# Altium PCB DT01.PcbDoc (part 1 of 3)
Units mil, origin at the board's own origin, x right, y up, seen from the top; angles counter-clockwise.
Board outline 2134.7 x 2226.1 mil, 2 copper layers (Top Layer, Bottom Layer), stack 57.918 mil thick; 95 components, 87 nets, 468 pads, 300 vias.
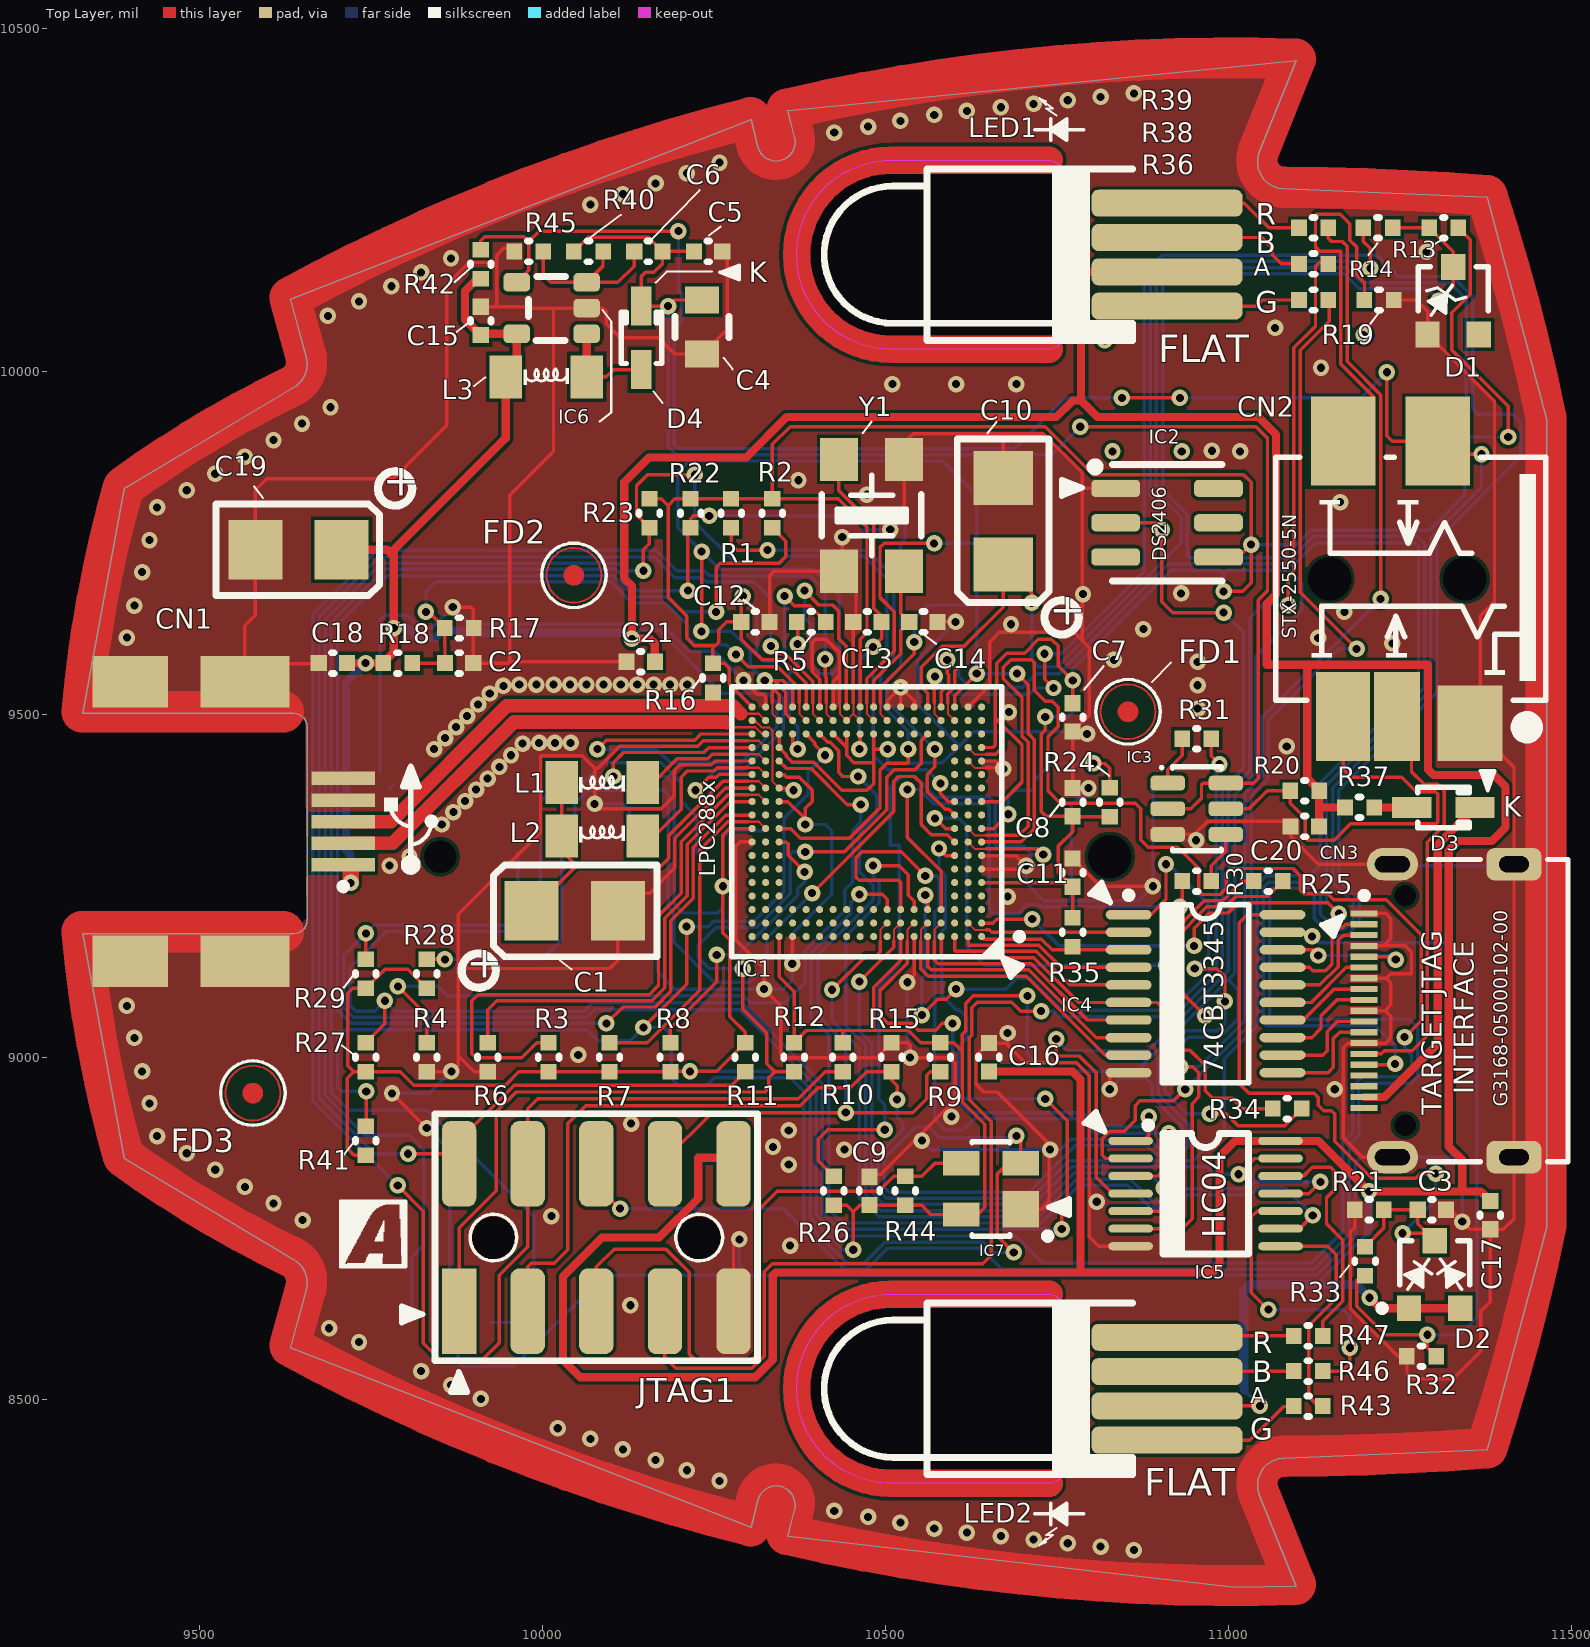
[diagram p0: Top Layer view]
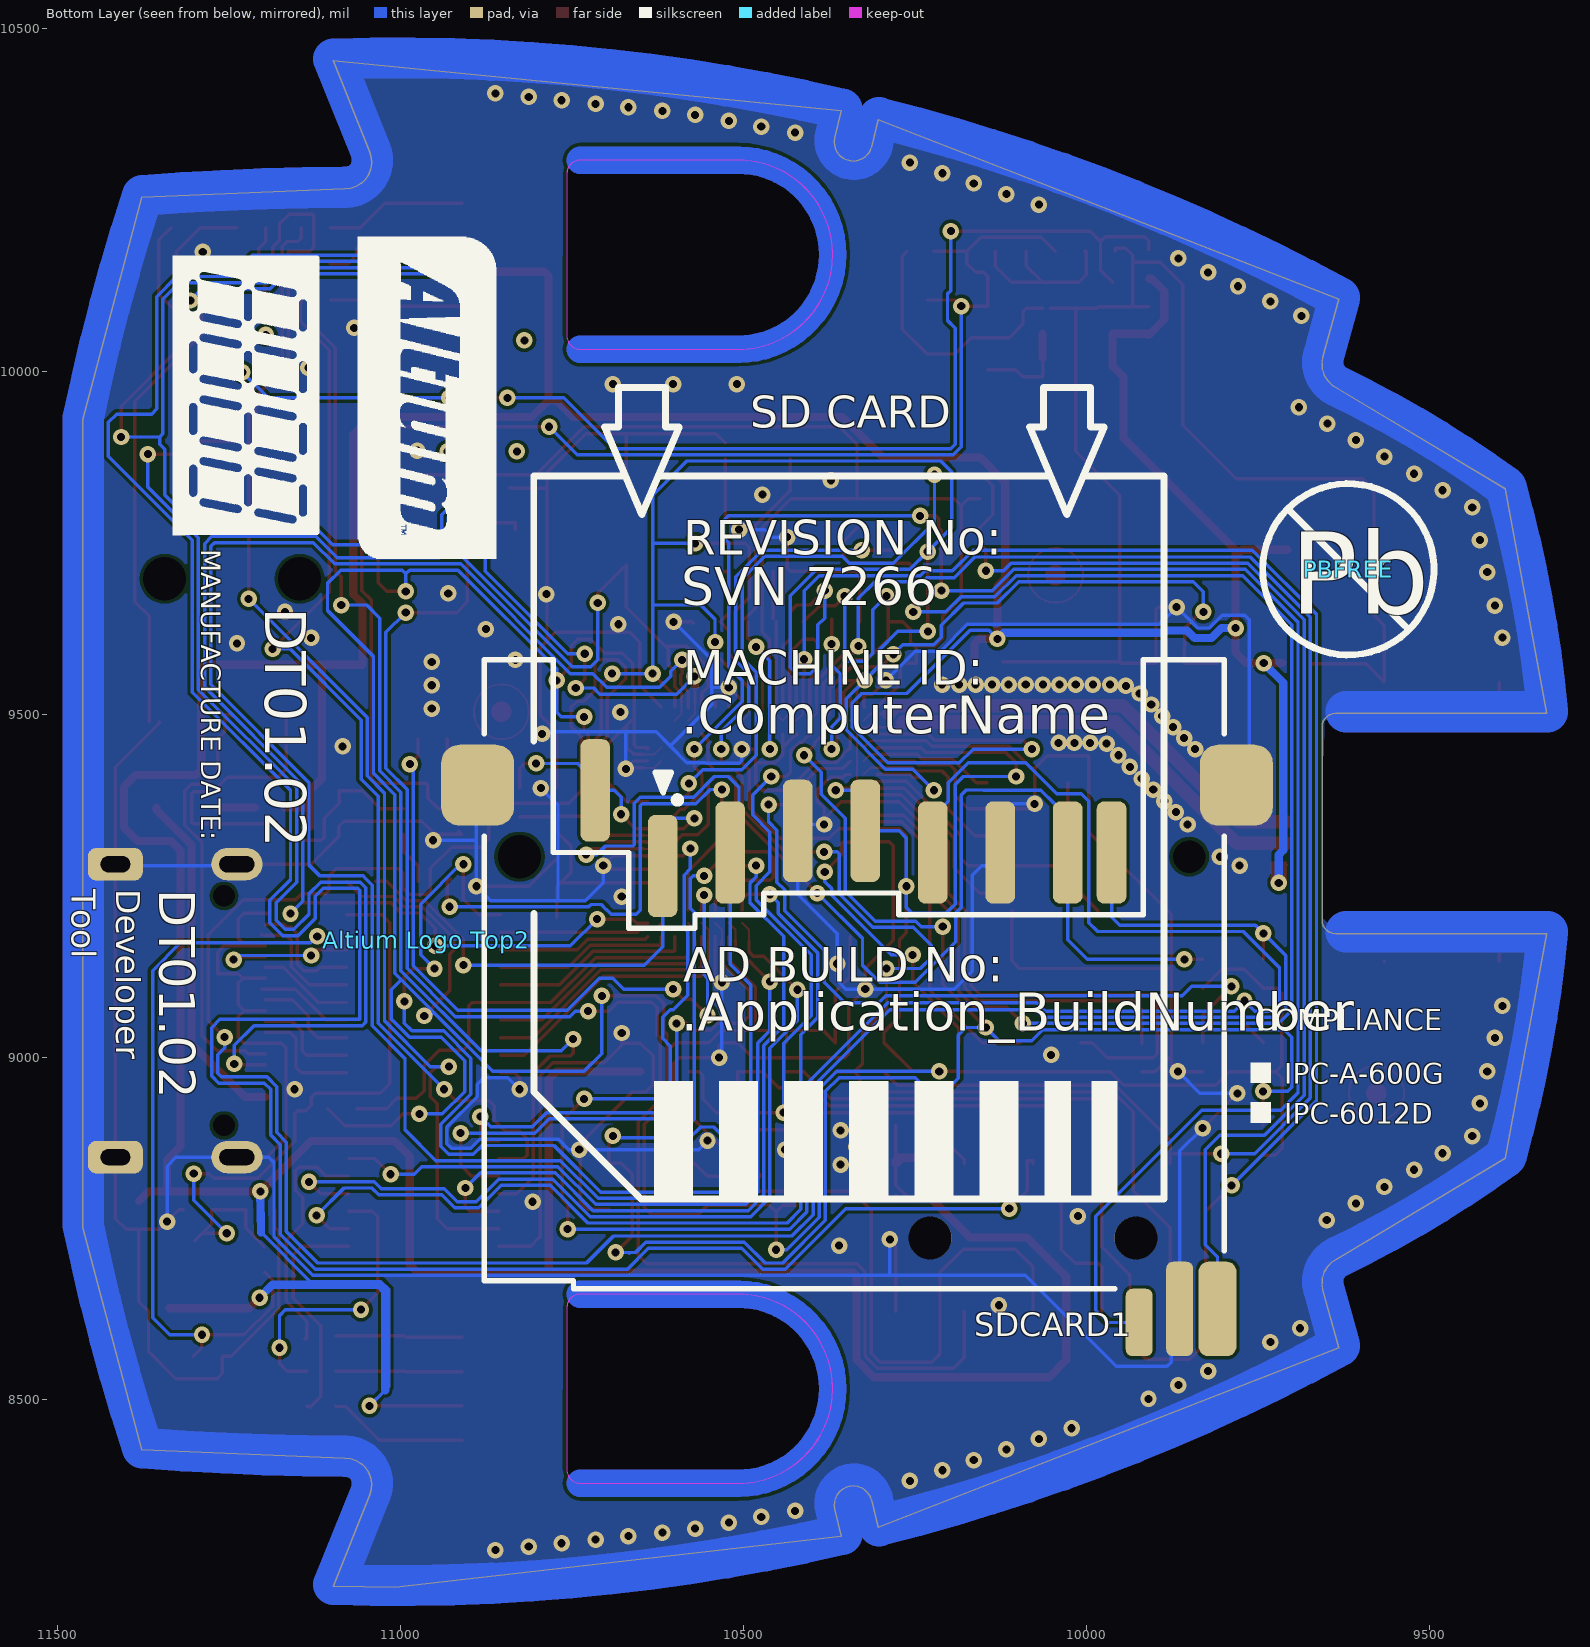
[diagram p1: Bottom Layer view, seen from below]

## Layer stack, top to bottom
Top Layer: signal copper 1.4
Dielectric: core 55.1181, FR-4, Dk 4.8
Bottom Layer: signal copper 1.4

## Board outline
9632.47,8576.36 9655.61,8660.1 9657,8669.12 9656.28,8678.21 9653.49,8686.9 9648.77,8694.71 9642.38,8701.23 9634.66,8706.09 9389.82,8852.38 9329.39,9180.02 9637.16,9180.02 9641.54,9180.52 9645.7,9181.97 9649.44,9184.32 9652.55,9187.43 9654.9,9191.17 9656.35,9195.33 9656.85,9199.71 9656.85,9481.2 9656.35,9485.58 9654.9,9489.74 9652.55,9493.48 9649.44,9496.59 9645.7,9498.94 9641.54,9500.39 9637.16,9500.89 9329.39,9500.89 9389.82,9828.53 9634.66,9974.82 9642.38,9979.68 9648.77,9986.2 9653.49,9994.01 9656.28,10002.7 9657,10011.79 9655.61,10020.81 9632.47,10104.55 10304.11,10366.84 10313.82,10327.29 10315.77,10321.87 10318.81,10316.97 10322.8,10312.81 10327.56,10309.57 10332.89,10307.39 10338.56,10306.37 10344.32,10306.55 10349.92,10307.93 10355.11,10310.43 10359.66,10313.96 10363.38,10318.36 10366.1,10323.44 10367.71,10328.97 10368.13,10334.72 10367.35,10340.43 10357.69,10379.8 11098.79,10452.79 11045.28,10319.67 11042.98,10311.48 11042.49,10302.98 11043.84,10294.58 11046.96,10286.67 11051.71,10279.61 11057.86,10273.73 11065.14,10269.32 11073.19,10266.57 11081.64,10265.62 11377.54,10253.65 11464.09,9929.39 11464.09,8751.52 11377.54,8427.26 11081.64,8415.29 11073.19,8414.34 11065.14,8411.59 11057.86,8407.18 11051.71,8401.3 11046.96,8394.24 11043.84,8386.33 11042.49,8377.93 11042.98,8369.43 11045.28,8361.24 11098.79,8228.12 11008.37,8226.7 10357.69,8301.11 10367.35,8340.48 10368.12,8345.97 10367.79,8351.49 10366.35,8356.84 10363.87,8361.79 10360.45,8366.15 10356.24,8369.74 10351.38,8372.41 10346.1,8374.06 10340.59,8374.61 10334.53,8373.94 10328.76,8371.95 10323.58,8368.74 10319.23,8364.47 10315.92,8359.35 10313.82,8353.62 10304.11,8314.07
cut-out: 10508.24,10032.02 cw(c10508.24,10169.82) 10508.24,10307.61 10738.55,10307.61 cw(c10738.55,10287.93) 10758.24,10287.93 10758.24,10051.71 cw(c10738.55,10051.71) 10738.55,10032.02
cut-out: 10508.24,8378.48 cw(c10508.24,8516.27) 10508.24,8654.07 10738.55,8654.07 cw(c10738.55,8634.38) 10758.24,8634.38 10758.24,8398.16 cw(c10738.55,8398.16) 10738.55,8378.48

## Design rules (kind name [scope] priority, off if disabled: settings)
Clearance [All] p1: gap=3
ComponentClearance [All] p1: gap=10 collisioncheckmode=3 verticalgap=9.21 showdistances=TRUE
FabricationTestPointUsage TestPointUsage [All] p1: valid=0 allowmultiple=FALSE
FabricationTestpoint Testpoint [All] p1: side=3 testpointundercomponent=TRUE minsize=40 maxsize=100 preferedsize=60 minholesize=0 maxholesize=40 preferedholesize=32 testpointgrid=1 allowsidetop=TRUE allowsidebottom=TRUE usegrid=TRUE gridtolerance=0.01
MinimumSolderMaskSliver [All] p1: minsoldermaskwidth=2.9
PolygonConnect [All] p1: connectstyle=Direct reliefconductorwidth=10 reliefentries=4 polygonreliefangle="90 Angle"
RoomDefinition U_Visual_Indicators [InComponentClass('U_Visual_Indicators')] p1: confinementstyle=ConfineIn formatcopy=TRUE lockcomponents=FALSE outline 10395.6,8376.32 10395.6,10309.87 11080.91,10309.87 11080.91,10239.02 11168.13,10239.02 11168.13,10073.73 11160.25,10073.73 11160.25,8460.95 11072.72,8460.95 11072.72,8376.32
RoomDefinition U_SD_Card_Socket [InComponentClass('U_SD_Card_Socket')] p2: confinementstyle=ConfineIn formatcopy=TRUE lockcomponents=FALSE outline 9712.34,8955.68 9712.34,9165.24 9717.12,9165.24 9717.12,9593.7 10125.87,9593.7 10125.87,9836.79 10245.89,9836.79 10245.89,9593.7 10952.72,9593.7 10952.72,9286.51 11102.19,9286.51 11102.19,9226.51 10952.72,9226.51 10952.72,8552.23 9717.12,8552.23 9717.12,8955.68
RoomDefinition U_Power_Bypass_Caps [InComponentClass('U_Power_Bypass_Caps')] p3: confinementstyle=ConfineIn formatcopy=TRUE lockcomponents=FALSE outline 9509.11,9657.72 9509.11,9821.58 10589.56,9821.58 10589.56,9916.06 10753.41,9916.06 10753.41,9539.11 10802.84,9539.11 10802.84,9366.21 11155.31,9366.21 11155.31,8813.39 11411.93,8813.39 11411.93,8725.43 11351.93,8725.43 11351.93,8760.87 10446.65,8760.87 10446.65,9544.34 9650.39,9544.34 9650.39,9657.72
RoomDefinition U_One-Wire_Write_Read [InComponentClass('U_One-Wire_Write_Read')] p4: confinementstyle=ConfineIn formatcopy=TRUE lockcomponents=FALSE outline 9879.87,10029.25 9879.87,10199.88 9935.73,10199.88 9935.73,10204.58 10285.46,10204.58 10285.46,10134.93 10286.91,10134.93 10286.91,10133.73 11263.57,10133.73 11263.57,9974.59 11553.33,9974.59 11553.33,9420.09 11155.33,9420.09 11155.33,9358.36 11032.72,9358.36 11032.72,9287.02 10997.89,9287.02 10997.89,9226.51 10909.89,9226.51 10909.89,9287.02 10875.07,9287.02 10875.07,9948.56 9911.14,9948.56 9911.14,10029.25
RoomDefinition U_Mini_USB_Socket [InComponentClass('U_Mini_USB_Socket')] p5: confinementstyle=ConfineIn formatcopy=TRUE lockcomponents=FALSE outline 9254.8,9090.36 9254.8,9595.84 9744.84,9595.84 9744.84,9604.34 9834.38,9604.34 9834.38,9655.51 9922.38,9655.51 9922.38,9596.67 10278.36,9596.67 10278.36,9508.67 9767.14,9508.67 9767.14,9090.36
RoomDefinition U_MCU_Debug [InComponentClass('U_MCU_Debug')] p6: confinementstyle=ConfineIn formatcopy=TRUE lockcomponents=FALSE outline 9816.28,8542.21 9816.28,8932.21 10336.28,8932.21 10336.28,8542.21
RoomDefinition U_MCU [InComponentClass('U_MCU')] p7: confinementstyle=ConfineIn formatcopy=TRUE lockcomponents=FALSE outline 9712.34,8834.13 9712.34,8922.13 9801.15,8922.13 9801.15,9043.68 9913.53,9043.68 9913.53,9295.14 9992.81,9295.14 9992.81,9458.72 10224.66,9458.72 10224.66,9591.16 10244.93,9591.16 10244.93,9836.79 10392.1,9836.79 10392.1,9914.33 10567.1,9914.33 10567.1,9664.36 10599.35,9664.36 10599.35,9591.16 10721.03,9591.16 10721.03,8890.64 10756.29,8890.64 10756.29,8719.06 10572.39,8719.06 10572.39,8760.85 10498.81,8760.85 10498.81,8834.13
RoomDefinition U_IO_Bus_Switch [InComponentClass('U_IO_Bus_Switch')] p8: confinementstyle=ConfineIn formatcopy=TRUE lockcomponents=FALSE outline 10742.84,9137.89 10742.84,9225.89 10799.23,9225.89 10799.23,9255.87 11134.19,9255.87 11134.19,8807.18 11340.68,8807.18 11340.68,8762.22 11367.35,8762.22 11367.35,8603.39 11325.56,8603.39 11325.56,8533.75 11237.56,8533.75 11237.56,8603.39 11204.12,8603.39 11204.12,8658.39 11169.29,8658.39 11169.29,8747.18 11161.19,8747.18 11041.74,8747.18 11041.74,8894.88 11041.74,8940.59 10799.23,8940.59 10799.23,9137.89
RoomDefinition U_Hard_Soft_JTAG_Socket [InComponentClass('U_Hard_Soft_JTAG_Socket')] p9: confinementstyle=ConfineIn formatcopy=TRUE lockcomponents=FALSE outline 11147.18,9334 11147.18,9394 11227.23,9394 11227.23,9407.23 11399.84,9407.23 11399.84,9316.28 11509.04,9316.28 11509.04,8818.87 11166.67,8818.87 11166.67,9334
RoomDefinition U_DT01_Mounts [InComponentClass('U_DT01_Mounts')] p10: confinementstyle=ConfineIn formatcopy=TRUE lockcomponents=FALSE outline 9518.12,8887.88 9518.12,9006.88 9518.12,9761.88 9986.12,9761.88 10105.12,9761.88 10105.12,9562.88 10913.12,9562.88 10913.12,9443.88 9637.12,9443.88 9637.12,8887.88
RoomDefinition DT01_ID [InComponentClass('DT01_ID')] p11: confinementstyle=ConfineIn formatcopy=TRUE lockcomponents=FALSE outline 10783.23,9679.01 10783.23,9882.81 11174.1,9882.81 11174.1,10239.02 11358.04,10239.02 11358.04,10182.16 11394.43,10182.16 11394.43,10023.33 11394.43,9679.01 11032.6,9679.01
RoutingVias [All] p1: holewidth=11.81 width=24 viastyle="Through Hole" minholewidth=11 minwidth=24 maxholewidth=12 maxwidth=28
SilkToSilkClearance SilkToSilkClearance_InvToFill [(ObjectKind = 'Text') And (TextKind <> 'Stroke Font') vs IsFill or Istrack] p1: silktosilkclearance=0
SilkToSilkClearance SilkToSilkClearance_Labels [(ObjectKind = 'Text') And (TextKind <> 'Stroke Font') vs (ObjectKind = 'Text') And (TextKind <> 'Stroke Font')] p2: silktosilkclearance=0
SilkToSilkClearance SilkToSilkClearance_Pb [(ObjectKind = 'Text') And (StringText = 'Pb') vs Istrack and onsilkscreen] p3: silktosilkclearance=0
SilkToSilkClearance SilkToSilkClearance_IC1 [incomponent('IC1') vs isdesignator] p4: silktosilkclearance=0
SilkToSilkClearance SilkToSilkClearance_+ [(ObjectKind = 'Text') And (StringText = '+') And (IsTextInverted = 'True') And (TextKind = 'TrueType Font') vs isarc and onsilkscreen] p5: silktosilkclearance=0
SilkToSilkClearance [All] p6: silktosilkclearance=4
SilkscreenOverComponentPads SilkscreenOverComponentPads_JTAG1 [isthrupin and InComponent('JTAG1') vs isarc and onsilkscreen] p1: minsilkscreentomaskgap=0
SilkscreenOverComponentPads SilkscreenOverComponentPads_LEDs [incomponent('LED1') or incomponent('LED2')] p2: minsilkscreentomaskgap=0
SilkscreenOverComponentPads [All] p3: minsilkscreentomaskgap=1
SolderMaskExpansion [All] p1: expansion=4
Width [All] p1: maxlimit=60 minlimit=3 preferedwidth=5
22 further rules are at their usual default settings.

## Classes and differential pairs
component class DT01_ID: D1 IC2 R13 R14
component class U_DT01_Mounts: FD1 FD2 FD3 PCB1
component class U_Hard_Soft_JTAG_Socket: CN3 D3 R37
component class U_IO_Bus_Switch: C3 D2 IC4 R21 R32 R33 R34 R35
component class U_MCU_Debug: JTAG1
component class U_MCU: C1 C13 C14 IC1 IC7 L1 L2 R1 R2 R3 R4 R5 R6 R7 R8 R9 R10 R11 R12 R15 R41 R44 Y1
component class U_Mini_USB_Socket: C2 CN1 R16 R17 R18
component class U_One-Wire_Write_Read: C4 C5 C6 C15 CN2 D4 IC3 IC6 L3 R19 R20 R30 R31 R40 R42 R45
component class U_Power_Bypass_Caps: C7 C8 C9 C10 C11 C12 C16 C17 C18 C19 C20 C21
component class U_SD_Card_Socket: R22 R23 R24 R25 R26 R27 R28 R29 SDCARD1
component class U_Visual_Indicators: IC5 LED1 LED2 R36 R38 R39 R43 R46 R47

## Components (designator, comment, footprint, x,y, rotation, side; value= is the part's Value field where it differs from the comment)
"Altium Logo Top2" "Generic No Pins" "NB2 ALTIUM LOGO" 10962.91,9170.78 r270 bottom (schematic designator "Altium Logo Top1")
C1 "47uF 10V" CAPC3528-STAR 10046.65,9213.21 r0 top locked (schematic designator C1_CP)
C2 "0.1uF 16V" CAPC1005-STAR 9878.38,9574.34 r180 top locked (schematic designator C1_US)
C3 "0.1uF 16V" CAPC1005-STAR 11296.7,8777.18 r0 top (schematic designator C13)
C4 "2.2uF 16V" CAPC2012-STAR 10232.62,10064.37 r90 top locked (schematic designator C3_12V)
C5 "0.1uF 16V" CAPC1005-STAR 10241.48,10174.58 r180 top locked (schematic designator C4_12V)
C6 "0.1uF 16V" CAPC1005-STAR 10154.22,10174.58 r0 top locked (schematic designator C2_12V)
C7 "0.1uF 16V" CAPC1005-STAR 10772.84,9495.13 r90 top locked (schematic designator C2_3V3)
C8 "0.1uF 16V" CAPC1005-STAR 10772.84,9371.64 r270 top (schematic designator C4_3V3)
C9 "0.1uF 16V" CAPC1005-STAR 10476.65,8804.85 r270 top locked (schematic designator C5_3V3)
C10 "47uF 10V" CAPC3528-STAR 10671.49,9780.98 r90 top locked (schematic designator C1_3V3)
C11 "0.1uF 16V" CAPC1005-STAR 10772.84,9268.82 r90 top (schematic designator C3_3V3)
C12 "0.1uF 16V" CAPC1005-STAR 10310.36,9634.36 r0 top locked (schematic designator C6_3V3)
C13 "39pF 50V 1005 COG" CAPC1005-STAR 10473.7,9634.36 r180 top locked (schematic designator C7_CP)
C14 "39pF 50V 1005 COG" CAPC1005-STAR 10555.37,9634.36 r0 top locked (schematic designator C8_CP)
C15 "0.1uF 16V" CAPC1005-STAR 9909.87,10073.23 r270 top locked (schematic designator C1_12V)
C16 "0.1uF 16V" CAPC1005-STAR 10650.82,8999.68 r270 top locked (schematic designator C2_5V0)
C17 "0.1uF 16V" CAPC1005-STAR 11381.93,8769.41 r90 top (schematic designator C4_5V0)
C18 "0.1uF 16V" CAPC1005-STAR 9694.37,9574.34 r0 top locked (schematic designator C5_5V0)
C19 "47uF 10V" CAPC3528-STAR 9644.19,9739.65 r180 top locked (schematic designator C1_5V0)
C20 "0.1uF 16V" CAPC1005-STAR 11111.33,9336.21 r180 top locked (schematic designator C3_5V0)
C21 "0.1uF 16V" CAPC1005-STAR 10143.08,9576.31 r180 top (schematic designator C6_5V0)
CN1 "0481900001" 481900001 9550.71,9343.1 r180 top locked (schematic designator CN1_US)
CN2 "PHONEJACK STEREO SW" STX-2550-5N-TR 11462.62,9697.34 r180 top locked
CN3 "HDMI19" G3168-0500XXXX-00 11455.73,9067.58 r0 top locked (schematic designator CN1)
D1 "3.3V" SOT95P230-3D 11327.81,10102.75 r0 top locked (schematic designator D1_ID)
D2 "BAV70TT1G" SOT95P230-3 11258.33,8628.59 r0 top (schematic designator D1)
D3 "ZHCS400" SOD323 11313.53,9363.76 r0 top locked (schematic designator D1_JTAG)
D4 "ZHCS400" SOD323 10144.06,10048.63 r90 top locked (schematic designator D1_12V)
FD1 "Fiducial - Round" "FIDUCIAL 2" 10853.62,9503.38 r90 top locked
FD2 "Fiducial - Round" "FIDUCIAL 2" 10045.62,9702.38 r90 top
FD3 "Fiducial - Round" "FIDUCIAL 2" 9577.62,8947.38 r90 top locked
IC1 "MC/ARM/LPC2888-SQ180" BGA50P18X18-180 9970.88,9844.94 r180 top locked (schematic designator IC1_CP)
IC2 "DS2406" TSOC6 10910.6,9779.01 r270 top locked (schematic designator IC1_ID)
IC3 "MAX4561" SOT23-6 10953.89,9361.98 r270 top locked (schematic designator IC1_1WB)
IC4 "SN74CBT3345CPWR" TSOP65P650-20 10966.71,9092.33 r0 top locked (schematic designator IC2)
IC5 "74VHC04" TSSOP14 10857.46,8877.66 r0 top locked (schematic designator IC1_LED)
IC6 "ZXLD1615" SOT-23-5 10064.36,10054.53 r90 top locked (schematic designator IC1_12V)
IC7 "MAX6315US26D1" SOT143 10653.77,8807.8 r90 top locked (schematic designator IC2_CP)
JTAG1 "TSM-105-01-S-DV" TSM-105-01-DV 9878.38,8844.21 r0 top locked (schematic designator JTAG)
L1 "10uH (LQH32CN100K33L)" 3261 10086.99,9400.17 r0 top locked (schematic designator L2_CP)
L2 "10uH (LQH32CN100K33L)" 3261 10086.99,9322.43 r0 top locked (schematic designator L1_CP)
L3 "10uH (LQH32CN100K33L)" 3261 10005.32,9991.56 r0 top locked (schematic designator L1_12V)
LED1 "RGB LED 5MM" LED-RGB-5MM-RA 10910.6,10244.87 r270 top locked
LED2 "RGB LED 5MM" LED-RGB-5MM-RA 10910.6,8591.32 r270 top locked
PBFREE "" LEAD_FREE_S 9618.6,9711.1 r180 bottom
R1 "4K7 1%" RESC1005-STAR 10274.93,9792.79 r90 top locked (schematic designator R13_CP)
R2 "4K7 1%" RESC1005-STAR 10334.96,9792.79 r90 top locked (schematic designator R14_CP)
R3 "4K7 1%" RESC1005-STAR 10008.76,8999.68 r270 top locked (schematic designator R4_CP)
R4 "12K 1%" RESC1005-STAR 9831.15,8999.68 r270 top (schematic designator R2_CP)
R5 "1K5 1%" RESC1005-STAR 10392.05,9634.36 r0 top (schematic designator R3_CP)
R6 "4K7 1%" RESC1005-STAR 9919.96,8999.68 r270 top locked (schematic designator R5_CP)
R7 "4K7 1%" RESC1005-STAR 10097.57,8999.68 r270 top locked (schematic designator R6_CP)
R8 "4K7 1%" RESC1005-STAR 10186.37,8999.68 r270 top locked (schematic designator R7_CP)
R9 "4K7 1%" RESC1005-STAR 10579.97,8999.68 r90 top locked (schematic designator R8_CP)
R10 "4K7 1%" RESC1005-STAR 10437.79,8999.68 r90 top locked (schematic designator R9_CP)
R11 "4K7 1%" RESC1005-STAR 10295.6,8999.68 r90 top locked (schematic designator R10_CP)
R12 "4K7 1%" RESC1005-STAR 10366.69,8999.68 r90 top locked (schematic designator R11_CP)
R13 "10K 1%" RESC1005-STAR 11314.04,10209.02 r0 top locked (schematic designator R1_ID)
R14 "1K 1%" RESC1005-STAR 11218.1,10209.02 r180 top locked (schematic designator R2_ID)
R15 "4K7 1%" RESC1005-STAR 10508.88,8999.68 r90 top locked (schematic designator R12_CP)
R16 "1M 1%" RESC1005-STAR 10248.36,9552.67 r90 top (schematic designator R1_US)
R17 "180K 1%" RESC1005-STAR 9878.38,9625.51 r0 top locked (schematic designator R3_US)
R18 "100K 1%" RESC1005-STAR 9788.84,9574.34 r180 top locked (schematic designator R2_US)
R19 "1K 1%" RESC1005-STAR 11219.57,10103.73 r0 top locked (schematic designator R4_1WB)
R20 "4K7 1%" RESC1005-STAR 11111.33,9388.36 r0 top locked (schematic designator R3_1WB)
R21 "1K 1%" RESC1005-STAR 11205.19,8777.18 r180 top (schematic designator R10)
R22 "4K7 1%" RESC1005-STAR 10215.89,9792.79 r90 top locked (schematic designator R15_CP)
R23 "4K7 1%" RESC1005-STAR 10155.87,9792.79 r90 top locked (schematic designator R16_CP)
R24 "4K7 1%" RESC1005-STAR 10826.95,9371.62 r270 top (schematic designator R17_CP)
R25 "4K7 1%" RESC1005-STAR 11058.19,9256.51 r0 top (schematic designator R18_CP)
R26 "4K7 1%" RESC1005-STAR 10424.49,8804.89 r270 top (schematic designator R19_CP)
R27 "4K7 1%" RESC1005-STAR 9742.34,8999.68 r270 top (schematic designator R20_CP)
R28 "4K7 1%" RESC1005-STAR 9831.15,9121.24 r270 top (schematic designator R21_CP)
R29 "4K7 1%" RESC1005-STAR 9742.34,9121.24 r270 top (schematic designator R22_CP)
R30 "100R 1%" RESC1005-STAR 10953.89,9256.51 r0 top (schematic designator R1_1WB)
R31 "100R 1%" RESC1005-STAR 10953.89,9464.13 r180 top locked (schematic designator R2_1WB)
R32 "4K7 1%" RESC1005-STAR 11281.56,8563.75 r0 top (schematic designator R27)
R33 "4K7 1%" RESC1005-STAR 11199.29,8702.39 r270 top (schematic designator R28)
R34 "4K7 1%" RESC1005-STAR 11085.74,8924.88 r0 top (schematic designator R26_CP)
R35 "4K7 1%" RESC1005-STAR 10772.84,9181.89 r90 top (schematic designator R25_CP)
R36 "150R 1%" RESC1005-STAR 11124.13,10103.73 r0 top locked (schematic designator R1_LED)
R37 "150R 1%" RESC1005-STAR 11191.18,9364 r0 top (schematic designator R1)
R38 "150R 1%" RESC1005-STAR 11124.13,10156.37 r0 top locked (schematic designator R2_LED)
R39 "150R 1%" RESC1005-STAR 11124.13,10209.02 r0 top locked (schematic designator R3_LED)
R40 "1M 1%" RESC1005-STAR 10066.99,10174.58 r180 top locked (schematic designator R2_12V)
R41 "4K7 1%" RESC1005-STAR 9742.34,8878.13 r270 top (schematic designator R23_CP)
R42 "10K 1%" RESC1005-STAR 9909.87,10155.88 r90 top locked (schematic designator R3_12V)
R43 "150R 1%" RESC1005-STAR 11116.25,8490.95 r0 top locked (schematic designator R4_LED)
R44 "4K7 1%" RESC1005-STAR 10528.81,8804.85 r270 top locked (schematic designator R1_CP)
R45 "91K 1%" RESC1005-STAR 9979.73,10174.58 r0 top locked (schematic designator R1_12V)
R46 "150R 1%" RESC1005-STAR 11116.25,8542.12 r0 top locked (schematic designator R5_LED)
R47 "150R 1%" RESC1005-STAR 11116.25,8593.29 r0 top (schematic designator R6_LED)
SDCARD1 "SDAMB-012" SDAMB-012 10334.92,9004.68 r0 bottom locked (schematic designator SDCARD)
Y1 "12MHz XTAL" XTAL-200X126-4 10479.6,9789.83 r270 top locked (schematic designator Y1_CP)

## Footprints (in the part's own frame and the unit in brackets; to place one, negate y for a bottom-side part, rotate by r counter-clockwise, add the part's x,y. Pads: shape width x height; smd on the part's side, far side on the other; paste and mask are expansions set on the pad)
3261 [mm] "3216 Chip; Chip Inductor; Body 3.2 x 1.6 mm (LxW typ)"
  rect 1.2x1.6 smd paste+0.038 mask+0.038: 1(-1.5,0) 2(1.5,0)
  body extent -1.63,-0.77 1.7,1.23, height 1.73
481900001 [mm] "Connector; USB Mini-B, Sinking Type, SM; 5 Position; Right Angle"
  rect 2.35x0.5 smd paste+0.038 mask+0.038: 1(-4.03,1.6) 2(-4.03,0.8) 3(-4.03,0) 4(-4.03,-0.8) 5(-4.03,-1.6)
  rect 3.302x1.905 smd paste+0.038 mask+0.038: MH1(-0.387,-5.175) MH4(-0.387,5.175)
  rect 2.794x1.905 smd paste+0.038 mask+0.038: MH2(3.863,-5.175) MH3(3.863,5.175)
  silkscreen extent -4.16,2.28 -3.91,2.52, body extent -4.5,-5.55 6.51,5.45, height 1.4
BGA50P18X18-180 [mil] "BGA, 180-Leads, Body 10x10mm, Pitch 0.5mm"
  round 10.5 smd paste+1.5 mask+1.5: A1(-669.29,669.29) A2(-649.61,669.29) A3(-629.92,669.29) A4(-610.24,669.29) A5(-590.55,669.29) A6(-570.87,669.29) A7(-551.18,669.29) A8(-531.5,669.29) A9(-511.81,669.29) A10(-492.13,669.29) A11(-472.44,669.29) A12(-452.76,669.29) A13(-433.07,669.29) A14(-413.39,669.29) A15(-393.7,669.29) A16(-374.02,669.29) A17(-354.33,669.29) A18(-334.65,669.29) B1(-669.29,649.61) B2(-649.61,649.61) B3(-629.92,649.61) B4(-610.24,649.61) B5(-590.55,649.61) B6(-570.87,649.61) B7(-551.18,649.61) B8(-531.5,649.61) B9(-511.81,649.61) B10(-492.13,649.61) B11(-472.44,649.61) B12(-452.76,649.61) B13(-433.07,649.61) B14(-413.39,649.61) B15(-393.7,649.61) B16(-374.02,649.61) B17(-354.33,649.61) B18(-334.65,649.61) C1(-669.29,629.92) C2(-649.61,629.92) C3(-629.92,629.92) C4(-610.24,629.92) C5(-590.55,629.92) C6(-570.87,629.92) C7(-551.18,629.92) C8(-531.5,629.92) C9(-511.81,629.92) C10(-492.13,629.92) C11(-472.44,629.92) C12(-452.76,629.92) C13(-433.07,629.92) C14(-413.39,629.92) C15(-393.7,629.92) C16(-374.02,629.92) C17(-354.33,629.92) C18(-334.65,629.92) D1(-669.29,610.24) D2(-649.61,610.24) D3(-629.92,610.24) D16(-374.02,610.24) D17(-354.33,610.24) D18(-334.65,610.24) E1(-669.29,590.55) E2(-649.61,590.55) E3(-629.92,590.55) E16(-374.02,590.55) E17(-354.33,590.55) E18(-334.65,590.55) F1(-669.29,570.87) F2(-649.61,570.87) F3(-629.92,570.87) F16(-374.02,570.87) F17(-354.33,570.87) F18(-334.65,570.87) G1(-669.29,551.18) G2(-649.61,551.18) G3(-629.92,551.18) G16(-374.02,551.18) G17(-354.33,551.18) G18(-334.65,551.18) H1(-669.29,531.5) H2(-649.61,531.5) H3(-629.92,531.5) H16(-374.02,531.5) H17(-354.33,531.5) H18(-334.65,531.5) J1(-669.29,511.81) J2(-649.61,511.81) J3(-629.92,511.81) J16(-374.02,511.81) J17(-354.33,511.81) J18(-334.65,511.81) K1(-669.29,492.13) K2(-649.61,492.13) K3(-629.92,492.13) K16(-374.02,492.13) K17(-354.33,492.13) K18(-334.65,492.13) L1(-669.29,472.44) L2(-649.61,472.44) L3(-629.92,472.44) L16(-374.02,472.44) L17(-354.33,472.44) L18(-334.65,472.44) M1(-669.29,452.76) M2(-649.61,452.76) M3(-629.92,452.76) M16(-374.02,452.76) M17(-354.33,452.76) M18(-334.65,452.76) N1(-669.29,433.07) N2(-649.61,433.07) N3(-629.92,433.07) N16(-374.02,433.07) N17(-354.33,433.07) N18(-334.65,433.07) P1(-669.29,413.39) P2(-649.61,413.39) P3(-629.92,413.39) P16(-374.02,413.39) P17(-354.33,413.39) P18(-334.65,413.39) R1(-669.29,393.7) R2(-649.61,393.7) R3(-629.92,393.7) R16(-374.02,393.7) R17(-354.33,393.7) R18(-334.65,393.7) T1(-669.29,374.02) T2(-649.61,374.02) T3(-629.92,374.02) T4(-610.24,374.02) T5(-590.55,374.02) T6(-570.87,374.02) T7(-551.18,374.02) T8(-531.5,374.02) T9(-511.81,374.02) T10(-492.13,374.02) T11(-472.44,374.02) T12(-452.76,374.02) T13(-433.07,374.02) T14(-413.39,374.02) T15(-393.7,374.02) T16(-374.02,374.02) T17(-354.33,374.02) T18(-334.65,374.02) U1(-669.29,354.33) U2(-649.61,354.33) U3(-629.92,354.33) U4(-610.24,354.33) U5(-590.55,354.33) U6(-570.87,354.33) U7(-551.18,354.33) U8(-531.5,354.33) U9(-511.81,354.33) U10(-492.13,354.33) U11(-472.44,354.33) U12(-452.76,354.33) U13(-433.07,354.33) U14(-413.39,354.33) U15(-393.7,354.33) U16(-374.02,354.33) U17(-354.33,354.33) U18(-334.65,354.33) V1(-669.29,334.65) V2(-649.61,334.65) V3(-629.92,334.65) V4(-610.24,334.65) V5(-590.55,334.65) V6(-570.87,334.65) V7(-551.18,334.65) V8(-531.5,334.65) V9(-511.81,334.65) V10(-492.13,334.65) V11(-472.44,334.65) V12(-452.76,334.65) V13(-433.07,334.65) V14(-413.39,334.65) V15(-393.7,334.65) V16(-374.02,334.65) V17(-354.33,334.65) V18(-334.65,334.65)
  silkscreen extent -729,305 -305,699, body extent -701,304 -305,700, height 20
CAPC1005-STAR [mm] "Chip Capacitor 1005"
  rect 0.6x0.6 smd paste+0.038 mask+0.038: 1(-0.525,0) 2(0.525,0)
  silkscreen extent -0.05,-0.38 0.05,0.38, body extent -0.76,-0.25 0.76,0.26, height 0.13
CAPC2012-STAR [mm] "0805 Capacitor SMD - Startronics"
  rrect0% 1x1.25 smd paste+0.038 mask+0.038: 1(-1,0) 2(1,0)
  silkscreen extent -0.4,-1 0.4,1, body extent -1.32,-0.55 1.24,0.6, height 0.13
CAPC3528-STAR [mm] "Capacitor 3.5x2.8mm (B-Case)"
  rect 2x2.2 smd paste+0.038 mask+0.038: 1(-1.6,0) 2(1.6,0)
  silkscreen extent -3,-1.7 3.05,1.7, body extent -1.77,-1.41 1.79,1.41, height 0.65
"FIDUCIAL 2" [mil]
  Top Layer circle w3: c0,0 r40
  Top Layer circle w18: c0,0 r6
  silkscreen extent -47,-47 47,47
G3168-0500XXXX-00 [mm] "3168 Series HDMI Type C, Female, Right-Angle, SMT"
  rect 1x0.23 smd paste+0.038 mask+0.038: 1(-6.55,3.6) 2(-6.55,3.2) 3(-6.55,2.8) 4(-6.55,2.4) 5(-6.55,2) 6(-6.55,1.6) 7(-6.55,1.2) 8(-6.55,0.8) 9(-6.55,0.4) 10(-6.55,0) 11(-6.55,-0.4) 12(-6.55,-0.8) 13(-6.55,-1.2) 14(-6.55,-1.6) 15(-6.55,-2) 16(-6.55,-2.4) 17(-6.55,-2.8) 18(-6.55,-3.2) 19(-6.55,-3.6)
  oval 1.9x1.2 hole 0.6 slot 1.3 at 0 deg paste+0.038 mask+0.038: MH1(-5.5,-5.425) MH4(-5.5,5.425)
  rrect50% 2.032x1.2 hole 0.6 slot 1.1 at 0 deg paste+0.038 mask+0.038: MH2(-1,-5.425) MH3(-1,5.425)
  round 0.5 hole 0.8 unplated paste+0.038 mask+0.038: MH5(-5.025,-4.25) MH6(-5.025,4.25)
  silkscreen extent -6.67,-5.6 1,5.6, body extent -6.25,-5.6 1,5.6, height 2.67
LEAD_FREE_S [mil]
  silkscreen extent -125,-125 125,125
LED-RGB-5MM-RA [mil] "LED RGB Right Angle 5mm"
  rrect50% 39.37x220 smd paste+1.5 mask+1.5: A(100,0) B(50,0) G(150,0) R(0,0)
  silkscreen extent -50,-500 200,-50, body extent -25,-487 174,97, height 100
"NB2 ALTIUM LOGO" [mil]
  silkscreen extent -1025,-99 -556,102
RESC1005-STAR [mm] "Chip Inductor 1005"
  rect 0.575x0.6 smd paste+0.038 mask+0.038: 1(-0.538,0) 2(0.538,0)
  silkscreen extent -0.05,-0.38 0.05,0.38, body extent -0.71,-0.25 0.71,0.25, height 0.25
SDAMB-012 [mm] "Connector; SD Card Type A, SM, 9 Position, Right Angle, Pitch 2.5 mm, Body 23.3 x 27.4 x 3.4 mm (LxWxH)"
  rrect50% 1.1x3.79 smd paste+0.038 mask+0.038: 1(7.2,-6.955) 2(4.7,-7.455) 3(2.2,-8.255) 4(-0.3,-8.255) 5(-2.8,-7.455) 6(-5.3,-7.455) 7(-7.8,-7.455) 8(-9.425,-7.455) 9(9.7,-9.755)
  rrect50% 2.7x3 smd paste+0.038 mask+0.038: MH1(14.05,-9.95) MH2(-14.05,-9.95)
  round 0.9 hole 1.2 unplated paste+0.038 mask+0.038: MH3(-12.3,-7.3)
  round 1.3 hole 1.6 unplated paste+0.038 mask+0.038: MH4(12.5,-7.3)
  rrect50% 1x3.5 smd paste+0.038 mask+0.038: SW1(-11.95,9.45)
  rrect50% 1.4x3.5 smd paste+0.038 mask+0.038: SW2(-13.35,9.45)
  rrect50% 1x2.5 smd paste+0.038 mask+0.038: SW3(-10.45,9.95)
  silkscreen extent -13.6,-14.6 13.8,8.7, body extent -13.6,-14.71 13.8,8.7, height 2.79
SOD323 [mm] "SOD-323/SC-76; 2 Leads; Body 1.7 x 1.3 mm, (LxW)"
  rect 1.45x0.762 smd paste+0.038 mask+0.038: 1(-1.175,0) 2(1.175,0)
  silkscreen extent -0.95,-0.75 0.95,0.75, body extent -0.97,-0.74 0.99,0.66, height 0.51
SOT23-6 [mm] "SOT-23/SC-74A; 5 Leads; Body 3.1 x 3 mm, inc. leads (LxW max)"
  rrect50% 0.55x1.27 smd paste+0.038 mask+0.038: 1(-0.95,-1.075) 2(0,-1.075) 3(0.95,-1.075) 4(0.95,1.075) 5(0,1.075) 6(-0.95,1.075)
  silkscreen extent -1.57,-1.35 1.55,0.9, body extent -1.3,-1.32 1.3,1.27, height 0.51
SOT95P230-3 [mm]
  rect 0.9x0.95 smd paste+0.038 mask+0.038: 1(0.127,0.127) 2(2.027,0.127) 3(1.077,2.627)
  silkscreen extent -1,0 2.38,2.63, body extent -0.18,-0.05 2.13,2.56, height 0.38
SOT95P230-3D [mm] "SOT23, 1=bottom-left, 2=top, 3=bottom-right"
  rect 0.9x0.95 smd paste+0.038 mask+0.038: 1(-0.95,-1.25) 2(0,1.25) 3(0.95,-1.25)
  silkscreen extent -1.3,-0.38 1.3,1.25, body extent -1.17,-1.35 1.14,1.29, height 0.38
SOT143 [mm] "SOT-143; 4 Leads; Body 3 x 2.6 mm, inc. leads (LxW max)"
  rect 1.35x1.35 smd paste+0.038 mask+0.038: 1(-0.75,-1.1)
  rect 0.9x1.35 smd paste+0.038 mask+0.038: 2(0.95,-1.1) 3(0.95,1.1) 4(-0.95,1.1)
  silkscreen extent -1.87,-2.23 1.75,0.7, body extent -1.5,-1.29 1.55,1.27, height 0.38
SOT-23-5 [mil] "SOT-23-5, 5-lead Small Outline Package"
  rrect50% 27x39 smd paste+1.5 mask+1.5: 1(0,0) 2(37.5,0) 3(75,0) 4(75,102) 5(0,102)
  silkscreen extent -10,31 83,85, body extent -4,2 80,104, height 10
STX-2550-5N-TR [mm] "STX-2550 Series Surface Mount 2.5mm Audio Jack"
  rect 2.4x2.8 smd paste+0.038 mask+0.038: 1(2.8,5.35)
  rect 2.4x3.3 smd paste+0.038 mask+0.038: 2(7.5,-5.1) 4(4,-5.1)
  rect 2x3.3 smd paste+0.038 mask+0.038: 3(7.5,5.1)
  rect 1.7x3.3 smd paste+0.038 mask+0.038: 5(5.5,5.1)
  round 1.3 hole 1.6 unplated paste+0.038 mask+0.038: MH1(3,0) MH2(8,0)
  silkscreen extent 0,-4.5 10,5.8, body extent -1.87,-4.49 9.99,4.45, height 4
TSM-105-01-DV [mil] "SMT 100mil space smt pin header"
  rect 50x125 smd paste+1.5 mask+1.5: 1(0,-215)
  rrect50% 50x125 smd paste+1.5 mask+1.5: 2(0,0) 3(100,-215) 4(100,0) 5(200,-215) 6(200,0) 7(300,-215) 8(300,0) 9(400,-215) 10(400,0)
  round 62.2 hole 62.99 paste+1.5 mask+1.5: PEGA(50,-108) PEGB(350,-108)
  silkscreen extent -35,-287 435,73, body extent -52,-253 448,37, height 380
TSOC6 [mil]
  rrect50% 25x71 smd paste+1.5 mask+1.5: 1(-50,-75) 2(0,-75) 3(50,-75) 4(50,75) 5(0,75) 6(-50,75)
  silkscreen extent -86,-110 85,80, body extent -82,-87 80,95, height 30
TSOP65P650-20 [mm] "TSOP, 20-Leads, Body 6.5x4.4mm, Pitch 0.65mm, IPC Medium Density"
  oval 1.7x0.35 smd paste+0.038 mask+0.038: 1(-2.85,2.925) 2(-2.85,2.275) 3(-2.85,1.625) 4(-2.85,0.975) 5(-2.85,0.325) 6(-2.85,-0.325) 7(-2.85,-0.975) 8(-2.85,-1.625) 9(-2.85,-2.275) 10(-2.85,-2.925) 11(2.85,-2.925) 12(2.85,-2.275) 13(2.85,-1.625) 14(2.85,-0.975) 15(2.85,-0.325) 16(2.85,0.325) 17(2.85,0.975) 18(2.85,1.625) 19(2.85,2.275) 20(2.85,2.925)
  silkscreen extent -2.97,-3.3 1.6,3.77, body extent -2.25,-3.3 2.25,3.3, height 1.2
TSSOP14 [mm]
  oval 1.65x0.3 smd paste+0.038 mask+0.038: 1(0,0) 2(0,-0.65) 3(0,-1.3) 4(0,-1.95) 5(0,-2.6) 6(0,-3.25) 7(0,-3.9) 8(5.55,-3.9) 9(5.55,-3.25) 10(5.55,-2.6) 11(5.55,-1.95) 12(5.55,-1.3) 13(5.55,-0.65) 14(5.55,0)
  silkscreen extent 0.52,-4.19 4.37,0.7, body extent -0.21,-4.45 6.18,0.56, height 0.64
XTAL-200X126-4 [mil] "CRYSTAL SMD 200x126x44 mils, 4 pads"
  rect 63x55 smd paste+1.5 mask+1.5: 1(-81.5,-47.5) 2(81.5,-47.5) 3(81.5,47.5) 4(-81.5,47.5)
  silkscreen extent -31,-72 31,72, body extent -82,-66 81,73, height 35

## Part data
C1 C10 C19: library part D-101-0001, "Capacitor, Tantalum, 47uF 20% 10V MCCT-B (3528-12)"
C2 C3 C5 C6 C7 C8 C9 C11 C12 C15 C16 C17 C18 C20 C21: library part D-101-0080, "Capacitor, Ceramic, 0.1uF 10% 16V 0402 (1005) X7R"
C4: library part D-101-0000, "Capacitor, Ceramic, 2.2uF 10% 16V 0805 (2012) X5R"
C13 C14: library part D-101-0089, "Capacitor, Ceramic, 18pF 5% 50V 0402 (1005) COG"
CN1: library part D-300-0034, "USB On-The-Go (OTG) Mini-B Receptacle, Right Angle, SMT, 0.80mm (.031\") Pitch, Solder Tabs with Back Cover, Recessed Type"
CN2: library part D-300-0059
CN3: library part D-300-0058, "HDMI Socket; 19 Pin"
D1: library part D-150-0005, "Zener Diode, 3.3V"
D2: library part D-155-0000, "Dual Switching Diode"
D3 D4: library part D-151-0004, "Schottky Diode, 400mA"
FD1 FD2 FD3: library part D-004-0001, "Fiducial - Round 1.5mm Top-Bottom"
IC1: library part D-242-0001, "16/32-bit ARM microcontrollers; 8 kB cache, up to 1 MB flash,  High Speed USB 2.0 device, and SDRAM memory interface"
IC2: library part D-263-0002, "Dual Addressable Switch Plus 1KB Memory"
IC3: library part D-200-0003, "±15kV ESD-Protected, Low-Voltage,  SPDT, CMOS Analog Switches"
IC4: library part D-205-0005, "SN74CBT3345CPWR; HIGH SPEED 8-BIT BUS SWITCH"
IC5: library part D-205-0004, "HEX Inverter"
IC6: library part D-204-0017, "ADJUSTABLE DC-DC BOOST CONVERTER WITH INTERNAL SWITCH IN  TSOT23-5"
IC7: library part D-243-0000, "MAX6315, Open-Drain Output SOT Reset IC, Customized Reset Thresholds, Timeout Delays"
JTAG1: library part D-300-0076, "Non-Boxed Header IDC, 2 X 5 Pin SMD"
L1 L2 L3: library part D-102-0011, "Inductor, 10uH, 450mA, 0.3R, 1210 (3225) LQH32CN100K33L"
LED1 LED2: library part D-153-0001, "LED, RGB, 5mm, 540R2GBC-CA, Common Anode"
R1 R2 R3 R6 R7 R8 R9 R10 R11 R12 R15 R20 R22 R23 R24 R25 R26 R27 R28 R29 R32 R33 R34 R35 R41 R44: library part D-100-0088, "Resistor, 4K7 1% 0402 (1005)"
R4: library part D-100-0002, "Resistor, 12K 1% 0402"
R5: library part D-100-0003, "Resistor, 1K5 1% 0402"
R13 R42: library part D-100-0130, "Resistor, 10K 1% 0402 (1005)"
R14 R19 R21: library part D-100-0121, "Resistor, 1K 1% 0402 (1005)"
R16 R40: library part D-100-0075, "Resistor, 1M 1% 0402"
R17: library part D-100-0006, "Resistor, 180K 1% 0402 (1005)"
R18: library part D-100-0132, "Resistor, 100K 1% 0402 (1005)"
R30 R31: library part D-100-0131, "Resistor, 100R 1% 0402 (1005)"
R36 R37 R38 R39 R43 R46 R47: library part D-100-0005, "Resistor, 150R 1% 0402 (1005)"
R45: library part D-100-0073, "Resistor, 91K 1% 0402"
SDCARD1: library part D-300-0018, "SDCARD Connector SDAMB-012"
Y1: library part D-103-0029, "Crystal, SMD, 12.000000MHz Stab=50ppm 10.0pF"

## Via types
v1: diameter 24, hole 11.81, Top Layer to Bottom Layer, tented both sides, 295 vias
v2: diameter 24.02, hole 11.81, Top Layer to Bottom Layer, tented both sides, 5 vias

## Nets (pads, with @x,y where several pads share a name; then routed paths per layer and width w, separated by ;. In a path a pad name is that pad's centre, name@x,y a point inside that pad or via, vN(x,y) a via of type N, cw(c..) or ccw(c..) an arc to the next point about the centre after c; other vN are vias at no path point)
1V8: IC1.H1 IC1.N18 IC1.U8 IC1.U9 IC1.U15 IC1.U16 IC1.V3 IC1.V11 IC1.V15 IC1.V16 | length 3545.7
  Top Layer w3: 10335,9520.1 10335,9500.5 IC1.U16@10344.89,9490.61 ; 10472.8,9516.79 10472.8,9500.5 IC1.U9@10482.69,9490.61 ; 10492.48,9516.79 10492.48,9500.5 IC1.U8@10502.37,9490.61
  Top Layer w5: v1(10223.01,9389.02) 10242.01,9408.02 10253.46,9408.02 10257.46,9412.02 10305.38,9412.02 IC1.N18@10305.52,9411.87 ; v1(10231.63,9620.57) 10232.01,9620.94 v1(10232.01,9737.02) ; 10335,9516.79 10335,9538.02 ; 10344.9,9519.02 IC1.V16@10344.89,9510.29 10344.89,9528.13 10335,9538.02 ; IC1.U15@10364.58,9490.61 10354.63,9500.55 10354.63,9532.01 10337.62,9549.02 ; v1(10382.01,9680.02) 10403.01,9659.02 10423.01,9659.02 10432.01,9650.02 10432.01,9610.02 10443.01,9599.02 10443.01,9510.29 IC1.V11@10443.32,9510.29 ; 10472.8,9516.79 10472.8,9551.81 10513.01,9592.02 10513.01,9649.02 10492.01,9670.02 10492.01,9743.02 10498.01,9749.02 v1(10571.01,9749.02) ; 10492.48,9516.79 10492.48,9538.5 10542.01,9588.02 v1(10542.01,9605.02) ; IC1.V3@10600.8,9510.29 10600.8,9526.81 v1(10633.01,9559.02) ; IC1.H1@10640.17,9313.44 10643.01,9313.44 10643.01,9314.02 10698.01,9314.02 10717.01,9333.02 10717.01,9462.73 10708.01,9471.73 10708.01,9543.02 v1(10692.01,9559.02) ; 10335,9538.02 v1(10324.01,9549.02) 10337.62,9549.02 ; 10337.62,9549.02 10350.28,9549.02 10364.58,9534.72 IC1.V15@10364.58,9512.45 ; IC1.V15@10364.58,9512.45 IC1.V15@10364.58,9510.29 10364.58,9509.02 10367.01,9509.02 10367.01,9510.02 10365.65,9511.37 IC1.V15@10364.58,9512.45
  Bottom Layer w5: v1(10223.01,9389.02) 10253.82,9419.83 10293.62,9419.83 10350.7,9476.9 10350.7,9522.33 v1(10324.01,9549.02) 10302.91,9570.12 10302.91,9593.09 10275.43,9620.57 v1(10231.63,9620.57) ; v1(10382.01,9680.02) 10382.01,9640.02 10392.01,9630.02 10392.01,9570.02 10403.01,9559.02 10423.01,9559.02 10432.37,9568.38 10432.37,9672.38 10393.75,9711 10258.02,9711 v1(10232.01,9737.02) 10197.01,9772.02 10197.01,9853.02 10213.01,9869.02 10583.01,9869.02 10633.01,9819.02 10633.01,9749.02 ; v1(10542.01,9605.02) 10542.01,9638.02 10563.01,9659.02 10633.01,9659.02 ; v1(10571.01,9749.02) 10633.01,9749.02 ; v1(10692.01,9559.02) v1(10633.01,9559.02) 10633.01,9659.02 ; 10633.01,9659.02 10633.01,9749.02
1WB: IC1.C4 R30.1 | length 810.5
  Top Layer w5: v1(10532.01,9390.02) 10532.01,9320.02 10581.12,9270.91 IC1.C4@10581.11,9215.02 ; R30.1@10927.01,9259.02 10932.71,9259.02 R30.1@10932.71,9256.51 10932.71,9222.71 v1(10929.02,9219.02)
  Bottom Layer w5: v1(10532.01,9390.02) 10549.28,9390.02 10570.28,9369.02 10648.28,9369.02 10651.01,9366.29 10651.01,9213.99 10657,9208 10693.43,9208 10700,9214.57 ; 10700.43,9215 10707.82,9222.4 10722.47,9222.4 10725.84,9219.02 ; 10726.55,9219.73 10727.26,9219.02 v1(10929.02,9219.02)
1WB+WR: CN2.5 CN3.14 | length 630.3
  Top Layer w5: CN3.14@11197.86,9004.59 11223.01,9004.59 11227.01,9008.59 ; 11227.01,9009.02 11267.78,9009.02 11290,9031.23 11290,9313.09 11315,9338.09 11315,9388 11305.5,9397.5 11285.51,9397.5 11267.01,9416 11267.01,9464.02 11257.01,9474.02 11257.01,9496.55 11257.01,9499.02 11246.09,9499.02 CN2.5@11246.09,9496.55
1WB_12V_TPP: IC1.C5 R31.1 | length 1037.6
  Top Layer w5: v1(10553.01,9061.02) 10576.37,9084.38 10588.37,9084.38 v1(10603.01,9099.02) ; v1(10558.01,9236.02) 10561.43,9232.6 IC1.C5@10561.43,9215.02 IC1.C5@10563.01,9215.02 ; R31.1@10975.07,9464.13 10975.07,9438.95 v1(10987.01,9427.02)
  Bottom Layer w5: v1@10553.01,9060.08 v1(10553.01,9061.02) 10553.01,9114.79 10558.01,9119.79 v1(10558.01,9236.02) ; v1(10603.01,9099.02) 10675.39,9099.02 10691.16,9114.79 10710.84,9114.79 10757.61,9068.02 10916.82,9068.02 10982,9133.2 10982,9422.01 v1(10987.01,9427.02)
1WW: IC2.2 JTAG1.7 R14.2 | length 3075.1
  Top Layer w5: JTAG1.7@10178.38,8629.21 10178.38,8561.9 10194.24,8546.04 10305.22,8546.04 10323.29,8564.1 10323.29,8686.9 10334.95,8698.56 10641.56,8698.56 10654.01,8711.01 10654.01,8905.67 10622.01,8937.67 10622.01,9028.02 10626,9032.01 10626,9072.02 10634,9080.02 10684,9080.02 10697.02,9067 v1(10727,9067) ; IC2.2@10833.01,9769.02 10833.01,9779.01 IC2.2@10835.6,9779.01 10893.01,9779.01 v1(10903.01,9769.02) 10903.01,9663.58 10918.57,9648.02 v1(10993.01,9648.02) ; R14.2@11196.92,10209.02 11196.92,10189.02 ; 11197.01,10189.02 11196.92,10189.02 ; v1(11207.01,10150.02) 11207.01,10178.93 11196.92,10189.02
  Bottom Layer w5: v1(10727,9067) 10745.9,9067 10753.89,9059.02 10920.55,9059.02 10991,9129.47 10991,9390 11022,9421 11022,9619.02 v1(10993.01,9648.02) ; v1(10903.01,9769.02) 10903.01,9802.39 10886.01,9819.39 10886.01,10138.4 10907.62,10160.02 11176.11,10160.02 11186.11,10150.02 v1(11207.01,10150.02)
3V3: C7.2 C8.2 C9.2 C10.1 C11.1 C12.1 IC1.A7 IC1.A16 IC1.E1 IC1.J18 IC1.L1 IC1.M16 IC1.R1 IC1.R2 IC1.R18 IC1.U3 IC1.U18 IC1.V5 IC1.V10 IC1.V14 IC1.V18 IC2.4 IC7.4 R1.2 R2.2 R3.2 R5.2 R7.2 R8.2 R9.2 R10.2 R11.2 R12.2 R13.2 R16.2 R22.2 R23.2 R24.2 R25.2 R26.2 R27.2 R28.2 R29.2 R34.2 R35.2 R41.2 R44.2 SDCARD1.4 | length 13029.2
  Top Layer w3: IC1.U18@10305.52,9490.61 10309.46,9490.61 10319.35,9480.72 10330.3,9480.72 10335.1,9475.92 10335.1,9401.98 IC1.M16@10344.89,9392.18 ; 10590.91,9516.79 10590.91,9500.5 IC1.U3@10600.8,9490.61 ; IC1.R2@10620.48,9451.24 10630.37,9441.35 10646.66,9441.35
  Top Layer w5: R41.2@9742.34,8856.95 9725.05,8856.95 9715,8867 9715,8969 9724.5,8978.5 ; R28.2@9831.15,9100.05 9803.2,9128 9770.29,9128 R29.2@9742.34,9100.05 9723.05,9100.05 9716,9093 9716,8987 9724.5,8978.5 ; v1(10103.01,9409.02) 10103.01,9429.02 10118.01,9444.02 10235.01,9444.02 10242.01,9451.02 IC1.R18@10303.01,9451.02 ; R23.2@10155.87,9813.97 10173.01,9813.97 10183.01,9803.97 ; R8.2@10186.37,8978.5 R7.2@10097.57,8978.5 R3.2@10008.76,8978.5 9965.49,8978.5 9946.01,8959.02 9811.98,8959.02 9792.5,8978.5 R27.2@9742.34,8978.5 9724.5,8978.5 ; R8.2@10186.37,8979.02 v1(10215.01,8979.02) 10253.75,8979.02 R11.2@10295.6,9020.86 10295.6,9036.43 10273.01,9059.02 10273.01,9170.88 10263.01,9180.88 v1(10263.01,9249.02) 10263.01,9323.56 10272.46,9333.02 IC1.J18@10305.52,9333.02 ; 10248,9600 10248.1,9599.9 ; v1(10292,9672) 10289.69,9669.69 C12.1@10289.69,9634.36 ; IC1.R18@10305.52,9451.24 10303.01,9451.24 IC1.R18@10303.01,9451.02 ; IC1.V18@10305.52,9510.29 10271.98,9543.84 10271.98,9567.02 10265.15,9573.85 R16.2@10248.36,9573.85 10248.36,9599.64 10248.1,9599.9 ; IC1.J18@10305.53,9333.02 IC1.J18@10305.52,9333.13 ; IC1.A16@10344.89,9175.65 10344.89,9117.13 10366.69,9095.33 R12.2@10366.69,9020.86 10384.51,9038.68 10439,9038.68 ; IC1.M16@10344.89,9392.18 10362.84,9392.18 v1(10366.01,9389.02) ; v1(10353,9672) 10367,9658 10389.59,9658 R5.2@10413.23,9634.36 ; IC1.V14@10384.01,9510.29 10384.01,9509.02 10384.26,9509.02 IC1.V14@10384.26,9510.29 10384.26,9544.76 10350.01,9579.02 10320.01,9579.02 10289.69,9609.34 C12.1@10289.69,9634.36 ; R26.2@10424.49,8783.71 10443.47,8783.71 10453.01,8774.18 ; R10.2@10437.79,9020.86 10437.79,9037.47 10439,9038.68 ; v1(10453.01,8719.02) 10453.01,8774.18 ; IC1.V10@10463,9510.29 10463,9609.02 10473.01,9619.02 10473.01,9772.33 10431.37,9813.97 R2.2@10334.96,9813.97 ; IC1.A7@10522.06,9175.65 10522.01,9175.59 10522.01,9141.02 10483,9102.01 10483,9038.68 ; 10532.67,9038.68 10483,9038.68 ; 10533.01,9039.02 10551.16,9020.86 R9.2@10579.97,9020.86 10599.66,9020.86 10612.01,9008.52 ; IC1.V5@10561.43,9510.29 10561.43,9530.6 10552.01,9540.02 10552.01,9568.02 10583.01,9599.02 10614.49,9599.02 ; 10590.91,9516.79 10590.91,9529.65 10601.01,9539.75 10601.01,9563.01 10610,9572 10610,9584.99 10610.01,9594.54 10614.49,9599.02 ; IC1.E1@10640.17,9254.39 10640.17,9254.02 C11.1@10766.97,9254.02 ; IC1.L1@10640.17,9372.02 IC1.L1@10640.17,9372.5 10670.49,9372.5 10699.01,9401.02 10699.01,9455.27 10670.5,9483.78 ; IC1.R1@10640.17,9449.02 IC1.R1@10640.17,9451.24 10656.38,9451.24 10660,9454.85 10660,9494.28 ; 10646.66,9441.35 10660.66,9441.35 10670.5,9451.19 10670.5,9483.78 ; C10.1@10671.49,9717.99 10671.49,9656.02 10614.49,9599.02 ; C10.1@10676.05,9713.42 10713.01,9676.47 v1(10713.01,9662.02) ; v1(10707.01,9089.02) 10628.02,9089.02 10617,9078 10617,9038.01 10612.01,9033.02 10612.01,9008.52 ; v1(10733.01,9496.02) 10733.01,9477 10727.01,9471 10727.01,9358 10734.03,9350.97 C8.2@10772.84,9350.97 10772.84,9328.49 10752.01,9307.66 10752.01,9268.98 C11.1@10766.97,9254.02 ; R35.2@10772.84,9203.07 C11.1@10772.84,9248.15 C11.1@10766.97,9254.02 ; C7.2@10772.84,9515.8 v1@10772.84,9548.85 ; v1(10773.01,9549.02) 10751.65,9570.37 10751.65,9599.37 10742,9609.02 10723,9609.02 10703,9589.02 10677.02,9589.02 10662.01,9574 10662.01,9539.09 10660,9537.08 10660,9494.28 ; C8.2@10773.37,9350.43 R24.2@10826.95,9350.43 ; v1(10966,9060) 10929,9097 10929,9150 10923,9156 10923,9173.27 10968.71,9218.98 10995.73,9218.98 11010.75,9234 11056.87,9234 R25.2@11079.37,9256.51 ; v1(10973,8917) 10997,8917 11014,8900 11082.05,8900 R34.2@11106.93,8924.88 ; IC2.4@10985.6,9729.01 11014.51,9729.01 v1@11032.76,9747.26 ; v1(10993.01,9679.02) 11020.8,9679.02 11033.01,9691.22 v1(11033.01,9747.02) ; v1@11033.01,9747.5 11033.01,9838.02 11022.01,9849.02 10803.01,9849.02 10733.01,9919.02 10360.83,9919.02 10334.95,9893.14 R2.2@10334.96,9813.97 ; R13.2@11335.22,10209.02 11352.78,10191.46 11352.78,10111.95 11325.84,10085.02 11325.84,10030.83 11408.01,9948.67 v1(11408.01,9904.02) ; 10183.01,9803.97 10183.01,9670 10210,9643.01 10210,9610.9 10221,9599.9 10248.1,9599.9 ; 10183.01,9803.97 10193.01,9813.97 R22.2@10215.89,9813.97 R1.2@10274.93,9813.97 R2.2@10334.96,9813.97 ; 10248.1,9599.9 10252.09,9599.9 10257.01,9604.82 10257.01,9623.02 10268.35,9634.36 C12.1@10289.69,9634.36 ; IC1.R18@10303.01,9451.02 10303.01,9450.02 10305.52,9450.02 10306.01,9450.02 10305.15,9450.87 10305.01,9451.02 IC1.R18@10303.01,9451.02 ; 10439,9038.68 10483,9038.68 ; 10453.01,8774.18 10463.01,8784.18 C9.2@10476.65,8784.18 10493.01,8784.18 10493.52,8783.67 R44.2@10528.81,8783.67 10553.01,8783.67 10566.27,8770.4 IC7.4@10610.47,8770.4 10634.39,8770.4 10645.01,8781.02 10645.01,8901.94 10612.01,8934.94 10612.01,9008.52 ; 10660,9494.28 10670.5,9483.78
  Bottom Layer w5: v1(10103.01,9409.02) 10180.28,9409.02 10192.01,9397.29 10192.01,9223.02 10199.22,9215.8 10205.01,9210.02 10255.01,9210.02 10263.01,9218.02 v1(10263.01,9249.02) 10263.01,9319.35 10273.33,9329.68 SDCARD1.4@10323.11,9329.68 ; v1(10215.01,8979.02) 10364.82,8979.02 10390.01,8953.83 10390.01,8766.56 10437.55,8719.02 v1(10453.01,8719.02) ; v1(10292,9672) 10312,9652 10312,9589 10324,9577 10352,9577 10353,9578 v1(10353,9672) ; SDCARD1.4@10343.01,9389.02 v1(10366.01,9389.02) ; v1(10707.01,9089.02) 10707.01,9005.02 10733.01,8979.02 10866.01,8979.02 10950.99,9064 ; v1(10713.01,9662.02) 10713.01,9579.02 10723.01,9569.02 10750.28,9569.02 10931.26,9750 10931.26,9786.86 10895.01,9823.11 10895.01,10134.67 10911.35,10151.02 11172.38,10151.02 11194.38,10129.02 11323.01,10129.02 11347.01,10105.02 11347.01,9908.52 11351.5,9904.02 ; v1(10733.01,9496.02) 10766.36,9496.02 10773.01,9502.66 v1(10773.01,9549.02) 10773.01,9566.29 10916.73,9710.02 10987.44,9710.02 10993.01,9704.45 v1(10993.01,9679.02) ; v1(10966,9060) 10950.99,9064 ; v1(10973,8917) 10939.46,8917 10907,8949.46 10907,8994.56 10941.44,9029 10987.53,9029 11014,9055.47 11014,9098.09 10999.54,9112.55 ; 10993.01,9704.95 10998.07,9710.02 11087.73,9710.02 11107.01,9690.75 11107.01,9651 11040,9583.99 11040,9413.54 11009,9382.54 11009,9122.01 10999.54,9112.55 ; v1(11033.01,9747.02) 11099.28,9747.02 11120.28,9768.02 11293.16,9768.02 11344.54,9819.39 11344.54,9886.25 11351.5,9893.22 11351.5,9904.02 ; v1(11408.01,9904.02) 11351.5,9904.02 ; 10950.99,9064 10956.49,9069.51 10999.54,9112.55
